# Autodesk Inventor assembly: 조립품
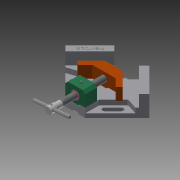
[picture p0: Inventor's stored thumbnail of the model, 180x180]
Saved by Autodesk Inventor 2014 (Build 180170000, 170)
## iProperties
Created: 2019-04
Part Number: 조립품
Document SubType Name: Assembly
Designer: kh
Author: kh
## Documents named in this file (11)
- C:\Users\kh\Desktop\490407V1024\답안조립품.iam
- C:\Users\kh\Desktop\490407V1024\본체.ipt
- C:\Users\kh\Desktop\490407V1024\리드스크류.ipt
- C:\Users\kh\Desktop\490407V1024\멈춤나사 M4x5.ipt
- C:\Users\kh\Desktop\490407V1024\멈춤나사 M4x10.ipt
- C:\Users\kh\Desktop\490407V1024\볼트 M4x16.ipt
- C:\Users\kh\Desktop\490407V1024\부시.ipt
- C:\Users\kh\Desktop\490407V1024\서포트.ipt
- C:\Users\kh\Desktop\490407V1024\조.ipt
- C:\Users\kh\Desktop\490407V1024\평행 핀 2.5x24.ipt
- C:\Users\kh\Desktop\490407V1024\핸들.ipt
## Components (1 placed, 1 different names)
1. 핸들:1 — Mate:4, Mate:5, Mate:6
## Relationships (3: Mate 3)
- Mate:4: 핸들:1
- Mate:5: 핸들:1
- Mate:6: 핸들:1
